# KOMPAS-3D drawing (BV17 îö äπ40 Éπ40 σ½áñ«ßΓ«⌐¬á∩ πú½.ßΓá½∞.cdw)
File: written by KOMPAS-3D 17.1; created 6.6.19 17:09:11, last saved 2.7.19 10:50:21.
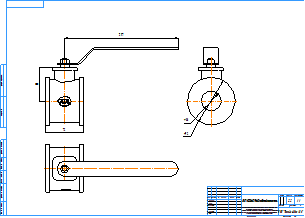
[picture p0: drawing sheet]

Sheet 1: A2, landscape

Title block, sheet 1: name: BV17 МФ Ду40 Ру40 хладостойкая угл.сталь; material: Сталь 20  ГОСТ 1050-2013; mass: 2,2; sheets: 1; sheet format: A2; stored path: C:\Users\kka\KOMPAS_Work\!Trash\BV17 МФ хладостойкая угл.сталь Ру40\KOMPAS 2D\BV17 МФ Ду20 Ру40 хладостойкая угл.сталь.cdw

Views: Вид 1, Проекционный вид 2, Проекционный вид 3
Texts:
  kka
  adl
  Рама для чертежей
  Лит-Масса-Масштаб
  Материал-Предприятие
  Масштаб
  Изм.
  Лист
  № докум.
  Подп.
  Дата
  Лит.
  Разраб.
  Пров.
  Т.контр.
  Листов
  Внимание! Данный продукт является объектом авторского права ООО «Торговый Дом АДЛ».
  Запрещается изменение, копирование, распространение
  (в том числе путем копирования на другие сайты и ресурсы в Интернете)
  или любое иное использование информации и объектов без предварительного
  согласия правообладателя (ООО «Торговый Дом АДЛ»).
  Н.контр.
  Утв.
  ООО "Торговый дом АДЛ"
  Изменение
  Номер документа
  Подпись
  Обозначение документа
  Наименование изделия
  Масса изделия по ГОСТ 2.109-73
  Порядковый номер листа
  Общее количество листов в документе
  Характер работы, выполненной лицом, подписавшим документ
  Наименование или индекс предприятия, выпускающего документ
  Инв. № подл.
  Подп. и дата
  Взам. инв. №
  Инв. № дубл.
  Инвентарный номер подлинника по ГОСТ 2.501-68
  Подпись принявшего подлинник в отдел технической документации
  Инвентарный номер подлинника, взамен которого выпущен данный подлинник
  Инвентарный номер дубликата по ГОСТ 2.502-68
  Подпись принявшего дубликат в отдел технической документации
  Справ. №
  Перв. примен.
  Обозначение документа, взамен или на основании которого выпущен данный документ
  Обозначение документа, в котором впервые записан данный документ
  Подпись лица, копировавшего чертеж
  Обозначение формата листа
  !Рама для чертежа
Dimensions and other numbers on the sheet: 72; 65; 217; 38; 92; 1:1; 1; 2,2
